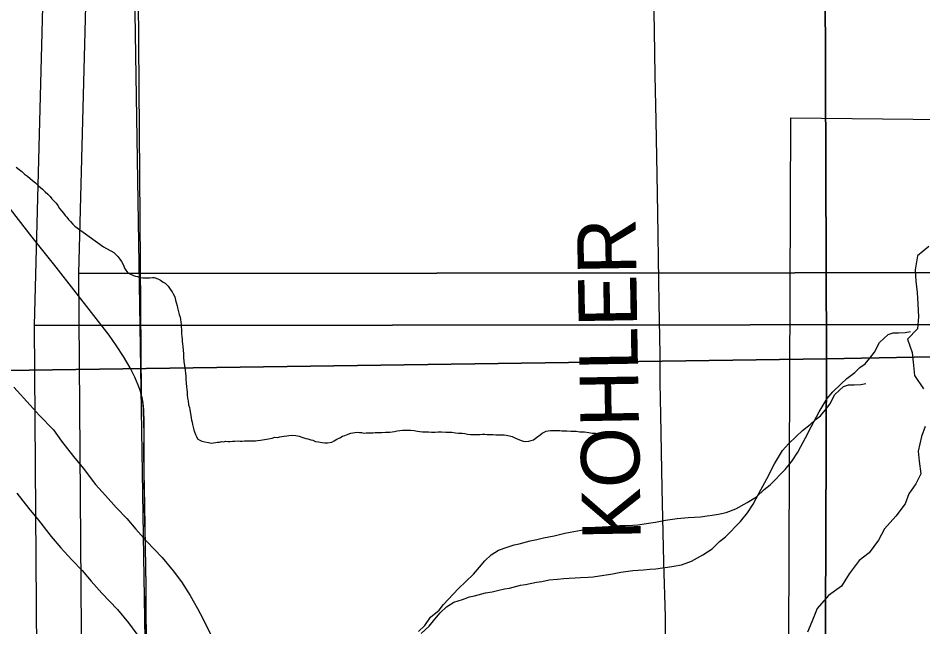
# Model space of a CAD drawing. Extents: x -21.1 to 50.3, y -4.9 to 22.1.
# Drawn here: x 2.7 to 3.578, y 18.66 to 19.251 of the extents above; entities that cross this region are included whole.
import ezdxf

# ---------------------------------------------------------------- set-up
doc = ezdxf.new("R2010")
doc.units = 0
for name, color, linetype in [('GM_X_Corporation', 7, 'Continuous'), ('GM_X_Major_River', 7, 'Continuous'), ('GM_X_Minor_River', 7, 'Continuous'), ('GM_X_Rail_Line_Text', 7, 'Continuous'), ('GM_X_Section', 7, 'Continuous'), ('GM_X_Township_Road', 7, 'Continuous'), ('GM_X_Township_Road_Text', 7, 'Continuous')]:
    doc.layers.add(name, color=color, linetype=linetype)

msp = doc.modelspace()

# ---------------------------------------------------------------- linework, layer by layer
at = {"layer": 'GM_X_Corporation'}
msp.add_lwpolyline([(2.1, 19.39131), (2.1, 18.37484), (2.82778, 18.38476), (2.81172, 19.39809)], close=True, dxfattribs=at)
at = {"layer": 'GM_X_Major_River'}
for points in [[(2.69604, 18.89307), (2.71209, 18.87573), (2.72089, 18.86592), (2.73464, 18.8516), (2.7423, 18.84065), (2.75416, 18.82593), (2.76335, 18.81461), (2.77559, 18.79875), (2.78515, 18.78781), (2.79586, 18.77612), (2.80579, 18.76557), (2.81459, 18.75538), (2.82491, 18.74369), (2.84019, 18.72786), (2.8509, 18.71503), (2.85894, 18.70408), (2.86738, 18.69086), (2.87429, 18.67838), (2.87968, 18.66855), (2.88776, 18.65229)], [(2.69901, 18.79013), (2.71088, 18.77541), (2.72006, 18.76409), (2.73231, 18.74824), (2.74187, 18.7373), (2.75257, 18.72561), (2.7625, 18.71505), (2.7713, 18.70487), (2.78162, 18.69318), (2.7969, 18.67735), (2.80761, 18.66452), (2.81566, 18.65357)]]:
    msp.add_lwpolyline(points, dxfattribs=at)
at = {"layer": 'GM_X_Minor_River'}
for points in [[(2.69845, 19.10638), (2.70145, 19.10405), (2.70408, 19.1021), (2.70669, 19.09977), (2.70932, 19.09782), (2.71194, 19.0955), (2.71418, 19.09356), (2.71718, 19.09122), (2.72017, 19.08851), (2.72391, 19.08502), (2.72652, 19.08269), (2.72914, 19.08036), (2.73138, 19.07804), (2.73324, 19.07573), (2.73548, 19.07341), (2.73734, 19.07148), (2.73882, 19.06917), (2.74067, 19.06648), (2.74253, 19.06417), (2.74438, 19.06185), (2.74586, 19.05955), (2.74773, 19.05799), (2.74921, 19.05569), (2.75108, 19.05375), (2.75331, 19.05105), (2.75555, 19.04911), (2.78332, 19.02911)], [(2.78332, 19.02911), (2.79331, 19.02381), (2.79706, 19.01995), (2.79892, 19.01726), (2.80079, 19.01495), (2.8019, 19.01266), (2.80301, 19.01036), (2.80374, 19.00845), (2.80486, 19.00653), (2.80672, 19.00384), (2.80862, 19.00306), (2.8124, 19.00148), (2.81429, 19.0007), (2.81618, 19.00029), (2.81808, 18.9995), (2.82149, 18.99908), (2.82339, 18.99905), (2.82606, 18.99901), (2.82834, 18.99898), (2.83063, 18.99933), (2.83253, 18.9993), (2.83442, 18.9989), (2.83669, 18.99772), (2.83858, 18.99694), (2.84122, 18.995), (2.8431, 18.99383), (2.84611, 18.99113), (2.84722, 18.98921), (2.84872, 18.98729), (2.84983, 18.98537), (2.85095, 18.98345), (2.85243, 18.98077), (2.85314, 18.97734), (2.85387, 18.97505), (2.85459, 18.972), (2.85495, 18.97009), (2.85676, 18.9636), (2.85748, 18.96092), (2.85783, 18.95864), (2.85818, 18.95597), (2.85853, 18.95406), (2.8585, 18.95216), (2.85883, 18.94836), (2.85878, 18.94493), (2.85913, 18.94226), (2.85948, 18.93998), (2.85944, 18.93732), (2.85979, 18.93503), (2.86013, 18.93236), (2.86047, 18.92893), (2.8608, 18.92551), (2.86075, 18.92208), (2.86108, 18.9179), (2.86178, 18.9137), (2.86249, 18.90951), (2.86282, 18.90646), (2.86317, 18.90417), (2.86312, 18.90075), (2.86345, 18.89694), (2.86379, 18.89351), (2.86413, 18.89085), (2.86448, 18.88856), (2.86444, 18.88552), (2.86477, 18.88247), (2.8655, 18.8798), (2.86583, 18.87599), (2.86655, 18.87332), (2.86691, 18.87141), (2.86725, 18.86912), (2.86797, 18.86569), (2.86832, 18.8634), (2.86866, 18.86112), (2.8694, 18.85921), (2.86975, 18.85692), (2.87009, 18.85425), (2.87082, 18.85158), (2.87155, 18.84967), (2.87266, 18.84699), (2.87339, 18.84508), (2.8745, 18.84278), (2.87677, 18.84161), (2.87866, 18.84082), (2.88169, 18.84002), (2.8851, 18.83921), (2.88776, 18.83879), (2.89004, 18.83914), (2.89386, 18.83985), (2.89576, 18.83982), (2.89766, 18.84018), (2.89957, 18.84015), (2.90148, 18.84051), (2.90376, 18.84048), (2.90604, 18.84044), (2.90833, 18.84079), (2.91061, 18.84076), (2.91403, 18.84109), (2.91593, 18.84069), (2.91783, 18.84066), (2.92012, 18.84101), (2.92316, 18.84097), (2.9262, 18.84093)], [(3.58415, 19.02958), (3.57315, 19.02047), (3.57087, 19.00682), (3.57162, 18.99582), (3.57276, 18.98482), (3.57351, 18.97382), (3.57426, 18.96131), (3.57312, 18.94955), (3.56364, 18.93969), (3.56818, 18.92679), (3.56893, 18.91731), (3.57044, 18.90442), (3.57915, 18.89152)], [(3.08893, 18.65601), (3.09497, 18.66176), (3.10061, 18.66979), (3.10891, 18.6767), (3.11305, 18.68206), (3.12737, 18.69738), (3.13491, 18.70467), (3.14246, 18.71158), (3.1481, 18.71847), (3.15337, 18.72459), (3.15941, 18.73035), (3.1666, 18.73497), (3.17494, 18.7377), (3.18176, 18.74003), (3.18669, 18.74122), (3.19732, 18.74396), (3.20377, 18.74516), (3.21022, 18.74673), (3.21554, 18.74791), (3.22047, 18.74871), (3.2311, 18.75146), (3.23603, 18.75226), (3.24666, 18.75425), (3.25198, 18.75505), (3.25919, 18.75663), (3.26717, 18.75746), (3.27325, 18.75789), (3.27857, 18.75831), (3.28427, 18.75874), (3.28959, 18.75878), (3.29681, 18.75922), (3.30175, 18.75964), (3.312, 18.76125), (3.31884, 18.76206), (3.32871, 18.76404), (3.3401, 18.76566), (3.35074, 18.7665), (3.35682, 18.76693), (3.36252, 18.76736), (3.36898, 18.76817), (3.37392, 18.76897), (3.37999, 18.76978), (3.38758, 18.77137), (3.39706, 18.77487), (3.40804, 18.78104), (3.41711, 18.78681), (3.42428, 18.79372), (3.43032, 18.79833), (3.44465, 18.81327), (3.45142, 18.8217), (3.45705, 18.83011), (3.46005, 18.83545), (3.46454, 18.84386), (3.47015, 18.85455), (3.47763, 18.86906), (3.48551, 18.88205), (3.49116, 18.88856), (3.4987, 18.89585), (3.50474, 18.9016), (3.51229, 18.90736), (3.5172, 18.91197), (3.52249, 18.91581), (3.52701, 18.92117), (3.53152, 18.92691), (3.53638, 18.93646), (3.54468, 18.94413), (3.54961, 18.94569), (3.55493, 18.94573)], [(3.55493, 18.94573), (3.5614, 18.94617), (3.56633, 18.94697)], [(3.09162, 18.65415), (3.09917, 18.66106), (3.10481, 18.66795), (3.11009, 18.67408), (3.11612, 18.67983), (3.12331, 18.68445), (3.13165, 18.68718), (3.13847, 18.68952), (3.14341, 18.6907), (3.15403, 18.69345), (3.16048, 18.69464), (3.16693, 18.69621), (3.17225, 18.6974), (3.17718, 18.6982), (3.18781, 18.70095), (3.19274, 18.70175), (3.20337, 18.70374), (3.20869, 18.70454), (3.2159, 18.70612), (3.22388, 18.70694), (3.22996, 18.70737), (3.23528, 18.70779), (3.24098, 18.70822), (3.2463, 18.70827), (3.25352, 18.70871), (3.25846, 18.70913), (3.26871, 18.71073), (3.27555, 18.71155), (3.28542, 18.71353), (3.29681, 18.71514), (3.30745, 18.71599), (3.31353, 18.71642), (3.31923, 18.71684), (3.32569, 18.71766), (3.33063, 18.71846), (3.3367, 18.71927), (3.3443, 18.72085), (3.35377, 18.72435), (3.36475, 18.73052), (3.37382, 18.7363), (3.38099, 18.7432), (3.38703, 18.74782), (3.40136, 18.76276), (3.40813, 18.77118), (3.41376, 18.77959), (3.41676, 18.78494), (3.42125, 18.79334), (3.42686, 18.80403), (3.43435, 18.81854), (3.44222, 18.83154), (3.44787, 18.83804), (3.45541, 18.84533), (3.46145, 18.85108), (3.469, 18.85685), (3.47391, 18.86145), (3.4792, 18.8653), (3.48372, 18.87066), (3.48823, 18.8764), (3.49309, 18.88594), (3.50139, 18.89361), (3.50632, 18.89518), (3.51164, 18.89522)], [(3.51164, 18.89522), (3.51811, 18.89565), (3.52304, 18.89645)], [(3.58065, 18.85473), (3.57723, 18.84525), (3.57381, 18.83084), (3.57495, 18.82136), (3.57646, 18.80884), (3.57152, 18.79936), (3.56469, 18.7895), (3.56128, 18.78001), (3.55217, 18.76788), (3.54118, 18.75574), (3.53548, 18.74474), (3.52638, 18.73222), (3.51652, 18.72501), (3.50704, 18.71212), (3.49945, 18.69998), (3.48694, 18.69088), (3.47594, 18.67836), (3.47062, 18.66546), (3.46645, 18.65522)], [(2.9262, 18.84093), (2.92811, 18.8409), (2.93077, 18.84086), (2.93267, 18.84122), (2.93572, 18.84156), (2.93953, 18.84226), (2.94335, 18.84297), (2.94678, 18.84369), (2.94945, 18.84441), (2.9525, 18.84437), (2.9544, 18.84472), (2.95631, 18.84508), (2.95859, 18.84543), (2.96126, 18.84577), (2.96317, 18.84612), (2.96622, 18.84646), (2.97002, 18.84603), (2.97305, 18.84561), (2.9757, 18.84443), (2.97949, 18.84324), (2.98138, 18.84283), (2.98441, 18.84203), (2.98631, 18.84162), (2.98896, 18.84044), (2.99199, 18.84002), (2.99541, 18.83921), (2.99807, 18.83918), (3.00073, 18.83914), (3.00492, 18.83984), (3.00722, 18.84095), (3.00952, 18.84244), (3.01259, 18.84392), (3.01527, 18.8454), (3.01756, 18.84613), (3.02062, 18.84761), (3.0233, 18.84834), (3.02711, 18.84904), (3.02978, 18.84939), (3.03167, 18.84898), (3.03358, 18.84896), (3.03585, 18.84854), (3.03814, 18.84889), (3.04042, 18.84886), (3.04308, 18.84883), (3.04499, 18.8488), (3.04689, 18.84915), (3.04917, 18.84912), (3.05107, 18.8491), (3.05336, 18.84906), (3.05678, 18.8494), (3.05868, 18.84937), (3.06097, 18.84934), (3.06325, 18.84969), (3.06554, 18.85004), (3.06821, 18.85076), (3.07088, 18.85111), (3.07355, 18.85145), (3.08115, 18.85134), (3.08457, 18.85092), (3.08799, 18.85049), (3.09026, 18.85008), (3.09292, 18.84966), (3.09558, 18.84962), (3.09863, 18.84958), (3.10167, 18.84954), (3.10509, 18.84949), (3.10814, 18.84983), (3.11118, 18.84979), (3.11536, 18.84935), (3.1184, 18.84931), (3.12144, 18.84927), (3.12486, 18.84884), (3.1279, 18.84842), (3.13132, 18.84837), (3.13398, 18.84795), (3.13663, 18.84754), (3.13929, 18.84712), (3.14233, 18.84708), (3.14537, 18.84704), (3.14842, 18.84699), (3.15108, 18.84734), (3.15337, 18.84731), (3.15565, 18.84727), (3.15907, 18.84723), (3.16135, 18.8472), (3.16401, 18.84678), (3.16629, 18.84675), (3.16933, 18.84671), (3.17199, 18.84667), (3.1739, 18.84664), (3.17731, 18.84584), (3.17996, 18.84504), (3.18185, 18.84425), (3.18525, 18.84268), (3.1879, 18.84151), (3.19055, 18.84071), (3.19283, 18.8403), (3.19587, 18.84064), (3.20046, 18.84209), (3.20353, 18.84433), (3.20699, 18.84695)], [(3.20699, 18.84695), (3.20891, 18.84844), (3.21274, 18.85029), (3.21465, 18.85065), (3.21694, 18.851), (3.2196, 18.85096), (3.22188, 18.85093), (3.22416, 18.8509), (3.22606, 18.85087), (3.22796, 18.85084), (3.23025, 18.85081), (3.23291, 18.85078), (3.23671, 18.85034), (3.23937, 18.8503), (3.24203, 18.85027), (3.24545, 18.84984), (3.25001, 18.84978), (3.25418, 18.84896), (3.2576, 18.84853), (3.2595, 18.84851), (3.26064, 18.84849), (3.26102, 18.84811)]]:
    msp.add_lwpolyline(points, dxfattribs=at)
at = {"layer": 'GM_X_Rail_Line_Text'}
msp.add_lwpolyline([(2.80304, 20.40853), (2.81087, 20.03185), (2.81277, 19.82639), (2.81993, 18.88501), (2.82032, 18.88348), (2.82138, 18.87729), (2.82193, 18.87105), (2.82227, 18.85861), (2.82233, 18.84925), (2.82223, 18.83065), (2.82232, 18.81077), (2.82296, 18.77819), (2.82368, 18.73759), (2.82432, 18.70035), (2.82424, 18.68173), (2.82467, 18.64449)], dxfattribs=at)
at = {"layer": 'GM_X_Section'}
for points in [[(3.82397, 20.01814), (3.83539, 19.00471), (3.80166, 19.0044), (2.75941, 19.00342), (2.78495, 19.98), (2.78619, 20.01563)], [(3.78068, 19.96762), (3.7921, 18.95419), (3.75837, 18.95389), (2.71612, 18.9529), (2.74167, 19.92948), (2.74291, 19.96511)], [(3.4813, 19.9322), (4.49957, 19.93786), (4.50668, 19.00183), (4.50596, 18.94006), (3.48506, 18.92038)], [(3.4813, 19.9322), (3.48506, 18.92038), (2.48311, 18.9064), (2.47214, 19.91783)], [(3.45029, 19.15441), (4.46024, 19.14326), (4.45293, 18.14262), (3.44648, 18.14125)], [(2.75941, 19.00342), (3.80166, 19.0044), (3.80452, 18.01477), (2.7666, 18.00853)], [(2.71612, 18.9529), (3.75837, 18.95389), (3.76124, 17.96425), (2.72331, 17.95801)], [(4.50596, 18.94006), (4.50247, 17.98887), (4.50289, 17.92975), (3.48086, 17.90781), (3.48506, 18.92038)], [(3.48506, 18.92038), (3.48086, 17.90781), (2.49066, 17.89119), (2.48311, 18.9064)]]:
    msp.add_lwpolyline(points, close=True, dxfattribs=at)
at = {"layer": 'GM_X_Township_Road'}
for points in [[(3.32827, 18.6207), (3.32853, 18.6704), (3.32711, 18.72317), (3.32547, 18.79467), (3.32409, 18.86615), (3.32353, 18.89722), (3.32334, 18.92512), (3.32264, 18.97469), (3.32224, 18.99643), (3.32111, 19.06171), (3.32057, 19.09898), (3.31973, 19.15181), (3.3187, 19.19532), (3.31812, 19.23883), (3.31662, 19.31031), (3.31621, 19.34746), (3.31522, 19.43445), (3.31448, 19.48418), (3.31441, 19.52144), (3.31391, 19.5556), (3.31429, 19.57735), (3.31433, 19.5824), (3.31441, 19.5987)], [(2.8136, 18.90259), (2.81318, 18.90354), (2.80899, 18.91192), (2.80274, 18.92271), (2.79599, 18.93318), (2.7888, 18.94336), (2.77155, 18.96537), (2.73727, 19.00948), (2.71402, 19.0386), (2.67373, 19.08984), (2.64498, 19.12647), (2.61277, 19.16826), (2.60311, 19.18042), (2.57526, 19.2138), (2.56163, 19.23069), (2.55038, 19.2455), (2.52512, 19.28084)], [(2.82014, 18.88446), (2.81899, 18.88902), (2.81694, 18.89496), (2.8136, 18.90259)], [(2.82938, 18.38508), (2.82908, 18.39103), (2.82907, 18.3937), (2.82913, 18.39879), (2.82904, 18.40811), (2.82858, 18.43602), (2.82812, 18.47016), (2.82733, 18.51361), (2.82726, 18.52291), (2.82686, 18.54154), (2.82579, 18.59118), (2.82488, 18.64395), (2.82445, 18.68118), (2.82453, 18.6998), (2.82389, 18.73705), (2.82317, 18.77765), (2.82253, 18.81023), (2.82244, 18.8301), (2.82254, 18.84871), (2.82248, 18.85807), (2.82214, 18.8705), (2.82159, 18.87674), (2.82053, 18.88293), (2.82014, 18.88446)]]:
    msp.add_lwpolyline(points, dxfattribs=at)

# ---------------------------------------------------------------- texts
at = {"layer": 'GM_X_Township_Road_Text'}
msp.add_text('KOHLER', height=0.056818, rotation=90.98222, dxfattribs=at).set_placement((3.30481, 18.745))

doc.saveas('drawing.dxf')
